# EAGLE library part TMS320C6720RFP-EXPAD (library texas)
Floating-Point Digital Signal Processors Source: http://focus.ti.com/lit/ds/symlink/tms320c6720.pdf
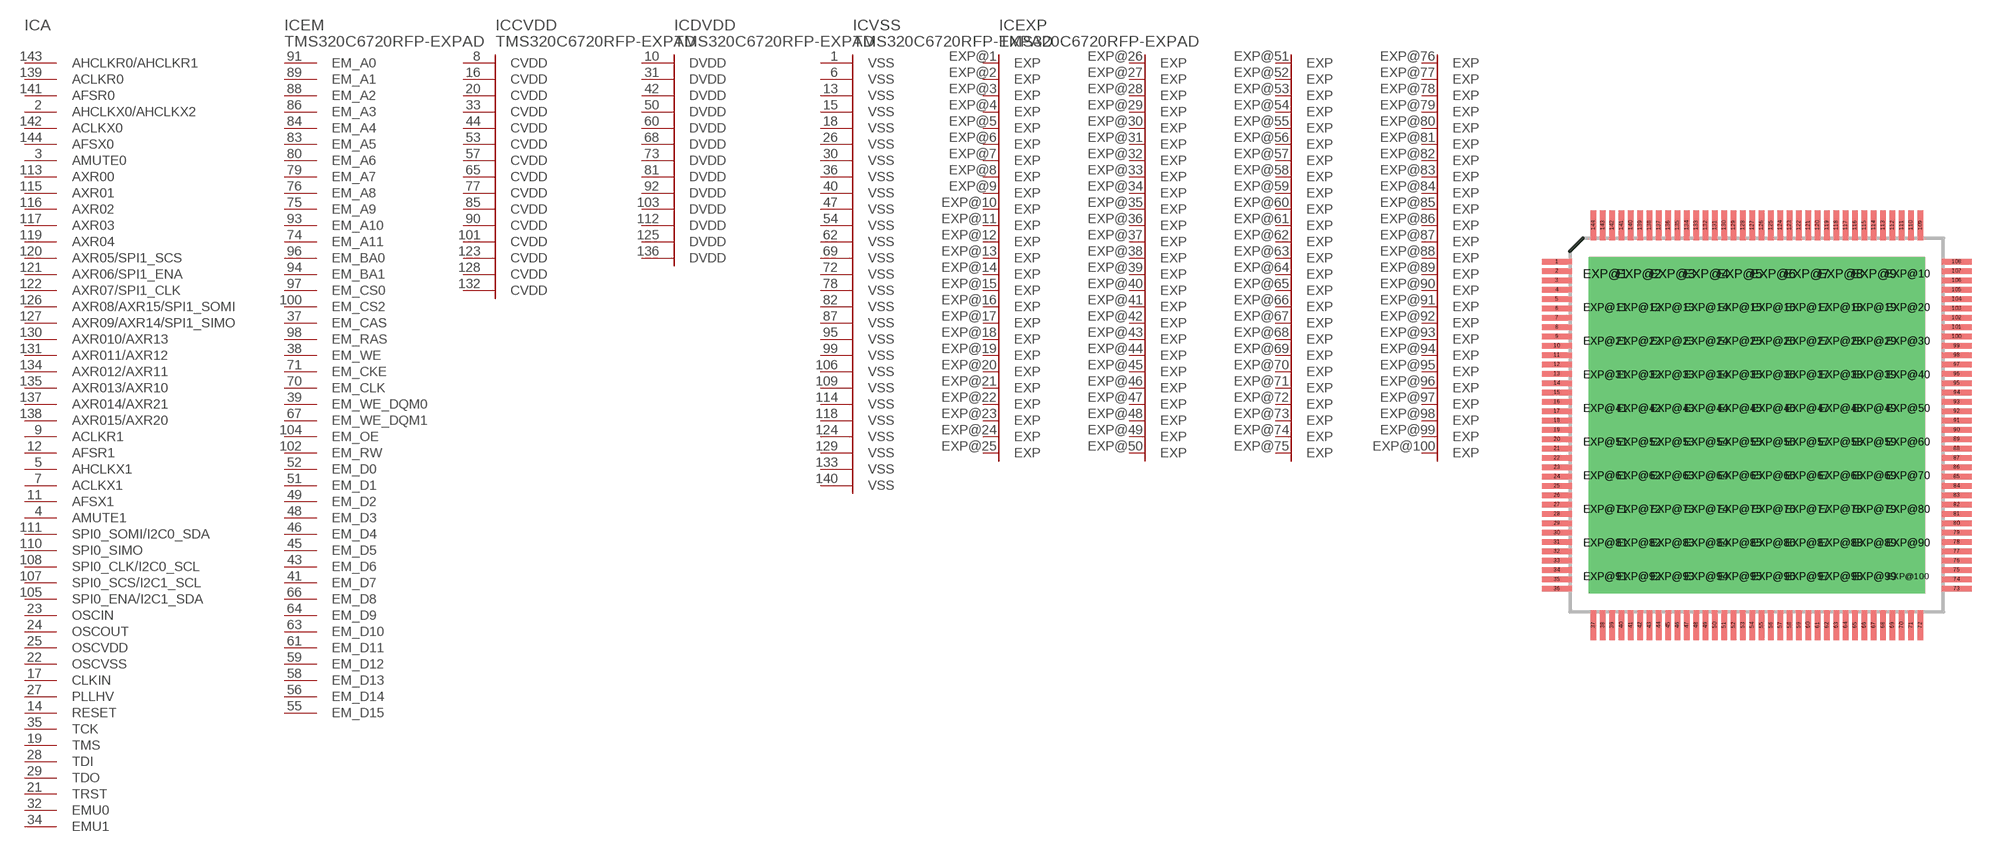
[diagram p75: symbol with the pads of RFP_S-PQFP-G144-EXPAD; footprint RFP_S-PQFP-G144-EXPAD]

Designator prefix IC; gates A=TMS320C6720-QFP-A EM=TMS320C6720-QFP-EM CVDD=TMS320C6720-QFP-CVDD DVDD=TMS320C6720-QFP-DVDD VSS=TMS320C6720-QFP-VSS EXP=EXP-100

## TMS320C6720RFP-EXPAD (OC_FARNELL: unknown; OC_NEWARK: unknown)  [RFP_S-PQFP-G144-EXPAD]
1  VSS:VSS  pwr
2  A:AHCLKX0/AHCLKX2
3  A:AMUTE0  out
4  A:AMUTE1  out
5  A:AHCLKX1
6  VSS:VSS  pwr
7  A:ACLKX1
8  CVDD:CVDD  pwr
9  A:ACLKR1
10  DVDD:DVDD  pwr
11  A:AFSX1
12  A:AFSR1
13  VSS:VSS  pwr
14  A:RESET  in
15  VSS:VSS  pwr
16  CVDD:CVDD  pwr
17  A:CLKIN  in
18  VSS:VSS  pwr
19  A:TMS  in
20  CVDD:CVDD  pwr
21  A:TRST  in
22  A:OSCVSS  pwr
23  A:OSCIN  in
24  A:OSCOUT  out
25  A:OSCVDD  pwr
26  VSS:VSS  pwr
27  A:PLLHV  pwr
28  A:TDI  in
29  A:TDO  hiz
30  VSS:VSS  pwr
31  DVDD:DVDD  pwr
32  A:EMU0
33  CVDD:CVDD  pwr
34  A:EMU1
35  A:TCK  in
36  VSS:VSS  pwr
37  EM:EM_CAS  out
38  EM:EM_WE  out
39  EM:EM_WE_DQM0  out
40  VSS:VSS  pwr
41  EM:EM_D7
42  DVDD:DVDD  pwr
43  EM:EM_D6
44  CVDD:CVDD  pwr
45  EM:EM_D5
46  EM:EM_D4
47  VSS:VSS  pwr
48  EM:EM_D3
49  EM:EM_D2
50  DVDD:DVDD  pwr
51  EM:EM_D1
52  EM:EM_D0
53  CVDD:CVDD  pwr
54  VSS:VSS  pwr
55  EM:EM_D15
56  EM:EM_D14
57  CVDD:CVDD  pwr
58  EM:EM_D13
59  EM:EM_D12
60  DVDD:DVDD  pwr
61  EM:EM_D11
62  VSS:VSS  pwr
63  EM:EM_D10
64  EM:EM_D9
65  CVDD:CVDD  pwr
66  EM:EM_D8
67  EM:EM_WE_DQM1  out
68  DVDD:DVDD  pwr
69  VSS:VSS  pwr
70  EM:EM_CLK  out
71  EM:EM_CKE  out
72  VSS:VSS  pwr
73  DVDD:DVDD  pwr
74  EM:EM_A11  out
75  EM:EM_A9  out
76  EM:EM_A8  out
77  CVDD:CVDD  pwr
78  VSS:VSS  pwr
79  EM:EM_A7  out
80  EM:EM_A6  out
81  DVDD:DVDD  pwr
82  VSS:VSS  pwr
83  EM:EM_A5  out
84  EM:EM_A4  out
85  CVDD:CVDD  pwr
86  EM:EM_A3  out
87  VSS:VSS  pwr
88  EM:EM_A2  out
89  EM:EM_A1  out
90  CVDD:CVDD  pwr
91  EM:EM_A0  out
92  DVDD:DVDD  pwr
93  EM:EM_A10  out
94  EM:EM_BA1  out
95  VSS:VSS  pwr
96  EM:EM_BA0  out
97  EM:EM_CS0  out
98  EM:EM_RAS  out
99  VSS:VSS  pwr
100  EM:EM_CS2  out
101  CVDD:CVDD  pwr
102  EM:EM_RW  out
103  DVDD:DVDD  pwr
104  EM:EM_OE  out
105  A:SPI0_ENA/I2C1_SDA
106  VSS:VSS  pwr
107  A:SPI0_SCS/I2C1_SCL
108  A:SPI0_CLK/I2C0_SCL
109  VSS:VSS  pwr
110  A:SPI0_SIMO
111  A:SPI0_SOMI/I2C0_SDA
112  DVDD:DVDD  pwr
113  A:AXR00
114  VSS:VSS  pwr
115  A:AXR01
116  A:AXR02
117  A:AXR03
118  VSS:VSS  pwr
119  A:AXR04
120  A:AXR05/SPI1_SCS
121  A:AXR06/SPI1_ENA
122  A:AXR07/SPI1_CLK
123  CVDD:CVDD  pwr
124  VSS:VSS  pwr
125  DVDD:DVDD  pwr
126  A:AXR08/AXR15/SPI1_SOMI
127  A:AXR09/AXR14/SPI1_SIMO
128  CVDD:CVDD  pwr
129  VSS:VSS  pwr
130  A:AXR010/AXR13
131  A:AXR011/AXR12
132  CVDD:CVDD  pwr
133  VSS:VSS  pwr
134  A:AXR012/AXR11
135  A:AXR013/AXR10
136  DVDD:DVDD  pwr
137  A:AXR014/AXR21
138  A:AXR015/AXR20
139  A:ACLKR0
140  VSS:VSS  pwr
141  A:AFSR0
142  A:ACLKX0
143  A:AHCLKR0/AHCLKR1
144  A:AFSX0
EXP@1  EXP:EXP  in
EXP@2  EXP:EXP  in
EXP@3  EXP:EXP  in
EXP@4  EXP:EXP  in
EXP@5  EXP:EXP  in
EXP@6  EXP:EXP  in
EXP@7  EXP:EXP  in
EXP@8  EXP:EXP  in
EXP@9  EXP:EXP  in
EXP@10  EXP:EXP  in
EXP@11  EXP:EXP  in
EXP@12  EXP:EXP  in
EXP@13  EXP:EXP  in
EXP@14  EXP:EXP  in
EXP@15  EXP:EXP  in
EXP@16  EXP:EXP  in
EXP@17  EXP:EXP  in
EXP@18  EXP:EXP  in
EXP@19  EXP:EXP  in
EXP@20  EXP:EXP  in
EXP@21  EXP:EXP  in
EXP@22  EXP:EXP  in
EXP@23  EXP:EXP  in
EXP@24  EXP:EXP  in
EXP@25  EXP:EXP  in
EXP@26  EXP:EXP  in
EXP@27  EXP:EXP  in
EXP@28  EXP:EXP  in
EXP@29  EXP:EXP  in
EXP@30  EXP:EXP  in
EXP@31  EXP:EXP  in
EXP@32  EXP:EXP  in
EXP@33  EXP:EXP  in
EXP@34  EXP:EXP  in
EXP@35  EXP:EXP  in
EXP@36  EXP:EXP  in
EXP@37  EXP:EXP  in
EXP@38  EXP:EXP  in
EXP@39  EXP:EXP  in
EXP@40  EXP:EXP  in
EXP@41  EXP:EXP  in
EXP@42  EXP:EXP  in
EXP@43  EXP:EXP  in
EXP@44  EXP:EXP  in
EXP@45  EXP:EXP  in
EXP@46  EXP:EXP  in
EXP@47  EXP:EXP  in
EXP@48  EXP:EXP  in
EXP@49  EXP:EXP  in
EXP@50  EXP:EXP  in
EXP@51  EXP:EXP  in
EXP@52  EXP:EXP  in
EXP@53  EXP:EXP  in
EXP@54  EXP:EXP  in
EXP@55  EXP:EXP  in
EXP@56  EXP:EXP  in
EXP@57  EXP:EXP  in
EXP@58  EXP:EXP  in
EXP@59  EXP:EXP  in
EXP@60  EXP:EXP  in
EXP@61  EXP:EXP  in
EXP@62  EXP:EXP  in
EXP@63  EXP:EXP  in
EXP@64  EXP:EXP  in
EXP@65  EXP:EXP  in
EXP@66  EXP:EXP  in
EXP@67  EXP:EXP  in
EXP@68  EXP:EXP  in
EXP@69  EXP:EXP  in
EXP@70  EXP:EXP  in
EXP@71  EXP:EXP  in
EXP@72  EXP:EXP  in
EXP@73  EXP:EXP  in
EXP@74  EXP:EXP  in
EXP@75  EXP:EXP  in
EXP@76  EXP:EXP  in
EXP@77  EXP:EXP  in
EXP@78  EXP:EXP  in
EXP@79  EXP:EXP  in
EXP@80  EXP:EXP  in
EXP@81  EXP:EXP  in
EXP@82  EXP:EXP  in
EXP@83  EXP:EXP  in
EXP@84  EXP:EXP  in
EXP@85  EXP:EXP  in
EXP@86  EXP:EXP  in
EXP@87  EXP:EXP  in
EXP@88  EXP:EXP  in
EXP@89  EXP:EXP  in
EXP@90  EXP:EXP  in
EXP@91  EXP:EXP  in
EXP@92  EXP:EXP  in
EXP@93  EXP:EXP  in
EXP@94  EXP:EXP  in
EXP@95  EXP:EXP  in
EXP@96  EXP:EXP  in
EXP@97  EXP:EXP  in
EXP@98  EXP:EXP  in
EXP@99  EXP:EXP  in
EXP@100  EXP:EXP  in

## Footprint RFP_S-PQFP-G144-EXPAD (pad centres in mm)
RFP_S-PQFP-G144 PowerPAD PLASTIC QUAD FLATPACK Source: http://focus.ti.com/lit/ds/symlink/tms320c6720.pdf Auto generated by make-symbol-device-package-bsdl.ulp Rev. 29
smd 1.6 x 0.3: 1 -10.7,8.75; 2 -10.7,8.25; 3 -10.7,7.75; 4 -10.7,7.25; 5 -10.7,6.75; 6 -10.7,6.25; 7 -10.7,5.75; 8 -10.7,5.25; 9 -10.7,4.75; 10 -10.7,4.25; 11 -10.7,3.75; 12 -10.7,3.25; 13 -10.7,2.75; 14 -10.7,2.25; 15 -10.7,1.75; 16 -10.7,1.25; 17 -10.7,0.75; 18 -10.7,0.25; 19 -10.7,-0.25; 20 -10.7,-0.75; 21 -10.7,-1.25; 22 -10.7,-1.75; 23 -10.7,-2.25; 24 -10.7,-2.75; 25 -10.7,-3.25; 26 -10.7,-3.75; 27 -10.7,-4.25; 28 -10.7,-4.75; 29 -10.7,-5.25; 30 -10.7,-5.75; 31 -10.7,-6.25; 32 -10.7,-6.75; 33 -10.7,-7.25; 34 -10.7,-7.75; 35 -10.7,-8.25; 36 -10.7,-8.75; 73 10.7,-8.75; 74 10.7,-8.25; 75 10.7,-7.75; 76 10.7,-7.25; 77 10.7,-6.75; 78 10.7,-6.25; 79 10.7,-5.75; 80 10.7,-5.25; 81 10.7,-4.75; 82 10.7,-4.25; 83 10.7,-3.75; 84 10.7,-3.25; 85 10.7,-2.75; 86 10.7,-2.25; 87 10.7,-1.75; 88 10.7,-1.25; 89 10.7,-0.75; 90 10.7,-0.25; 91 10.7,0.25; 92 10.7,0.75; 93 10.7,1.25; 94 10.7,1.75; 95 10.7,2.25; 96 10.7,2.75; 97 10.7,3.25; 98 10.7,3.75; 99 10.7,4.25; 100 10.7,4.75; 101 10.7,5.25; 102 10.7,5.75; 103 10.7,6.25; 104 10.7,6.75; 105 10.7,7.25; 106 10.7,7.75; 107 10.7,8.25; 108 10.7,8.75
smd 0.3 x 1.6: 37 -8.75,-10.7; 38 -8.25,-10.7; 39 -7.75,-10.7; 40 -7.25,-10.7; 41 -6.75,-10.7; 42 -6.25,-10.7; 43 -5.75,-10.7; 44 -5.25,-10.7; 45 -4.75,-10.7; 46 -4.25,-10.7; 47 -3.75,-10.7; 48 -3.25,-10.7; 49 -2.75,-10.7; 50 -2.25,-10.7; 51 -1.75,-10.7; 52 -1.25,-10.7; 53 -0.75,-10.7; 54 -0.25,-10.7; 55 0.25,-10.7; 56 0.75,-10.7; 57 1.25,-10.7; 58 1.75,-10.7; 59 2.25,-10.7; 60 2.75,-10.7; 61 3.25,-10.7; 62 3.75,-10.7; 63 4.25,-10.7; 64 4.75,-10.7; 65 5.25,-10.7; 66 5.75,-10.7; 67 6.25,-10.7; 68 6.75,-10.7; 69 7.25,-10.7; 70 7.75,-10.7; 71 8.25,-10.7; 72 8.75,-10.7; 109 8.75,10.7; 110 8.25,10.7; 111 7.75,10.7; 112 7.25,10.7; 113 6.75,10.7; 114 6.25,10.7; 115 5.75,10.7; 116 5.25,10.7; 117 4.75,10.7; 118 4.25,10.7; 119 3.75,10.7; 120 3.25,10.7; 121 2.75,10.7; 122 2.25,10.7; 123 1.75,10.7; 124 1.25,10.7; 125 0.75,10.7; 126 0.25,10.7; 127 -0.25,10.7; 128 -0.75,10.7; 129 -1.25,10.7; 130 -1.75,10.7; 131 -2.25,10.7; 132 -2.75,10.7; 133 -3.25,10.7; 134 -3.75,10.7; 135 -4.25,10.7; 136 -4.75,10.7; 137 -5.25,10.7; 138 -5.75,10.7; 139 -6.25,10.7; 140 -6.75,10.7; 141 -7.25,10.7; 142 -7.75,10.7; 143 -8.25,10.7; 144 -8.75,10.7
drill 0.3 pad 1.8 square: EXP@1 -8.1,8.1; EXP@2 -6.3,8.1; EXP@3 -4.5,8.1; EXP@4 -2.7,8.1; EXP@5 -0.9,8.1; EXP@6 0.9,8.1; EXP@7 2.7,8.1; EXP@8 4.5,8.1; EXP@9 6.3,8.1; EXP@10 8.1,8.1; EXP@11 -8.1,6.3; EXP@12 -6.3,6.3; EXP@13 -4.5,6.3; EXP@14 -2.7,6.3; EXP@15 -0.9,6.3; EXP@16 0.9,6.3; EXP@17 2.7,6.3; EXP@18 4.5,6.3; EXP@19 6.3,6.3; EXP@20 8.1,6.3; EXP@21 -8.1,4.5; EXP@22 -6.3,4.5; EXP@23 -4.5,4.5; EXP@24 -2.7,4.5; EXP@25 -0.9,4.5; EXP@26 0.9,4.5; EXP@27 2.7,4.5; EXP@28 4.5,4.5; EXP@29 6.3,4.5; EXP@30 8.1,4.5; EXP@31 -8.1,2.7; EXP@32 -6.3,2.7; EXP@33 -4.5,2.7; EXP@34 -2.7,2.7; EXP@35 -0.9,2.7; EXP@36 0.9,2.7; EXP@37 2.7,2.7; EXP@38 4.5,2.7; EXP@39 6.3,2.7; EXP@40 8.1,2.7; EXP@41 -8.1,0.9; EXP@42 -6.3,0.9; EXP@43 -4.5,0.9; EXP@44 -2.7,0.9; EXP@45 -0.9,0.9; EXP@46 0.9,0.9; EXP@47 2.7,0.9; EXP@48 4.5,0.9; EXP@49 6.3,0.9; EXP@50 8.1,0.9; EXP@51 -8.1,-0.9; EXP@52 -6.3,-0.9; EXP@53 -4.5,-0.9; EXP@54 -2.7,-0.9; EXP@55 -0.9,-0.9; EXP@56 0.9,-0.9; EXP@57 2.7,-0.9; EXP@58 4.5,-0.9; EXP@59 6.3,-0.9; EXP@60 8.1,-0.9; EXP@61 -8.1,-2.7; EXP@62 -6.3,-2.7; EXP@63 -4.5,-2.7; EXP@64 -2.7,-2.7; EXP@65 -0.9,-2.7; EXP@66 0.9,-2.7; EXP@67 2.7,-2.7; EXP@68 4.5,-2.7; EXP@69 6.3,-2.7; EXP@70 8.1,-2.7; EXP@71 -8.1,-4.5; EXP@72 -6.3,-4.5; EXP@73 -4.5,-4.5; EXP@74 -2.7,-4.5; EXP@75 -0.9,-4.5; EXP@76 0.9,-4.5; EXP@77 2.7,-4.5; EXP@78 4.5,-4.5; EXP@79 6.3,-4.5; EXP@80 8.1,-4.5; EXP@81 -8.1,-6.3; EXP@82 -6.3,-6.3; EXP@83 -4.5,-6.3; EXP@84 -2.7,-6.3; EXP@85 -0.9,-6.3; EXP@86 0.9,-6.3; EXP@87 2.7,-6.3; EXP@88 4.5,-6.3; EXP@89 6.3,-6.3; EXP@90 8.1,-6.3; EXP@91 -8.1,-8.1; EXP@92 -6.3,-8.1; EXP@93 -4.5,-8.1; EXP@94 -2.7,-8.1; EXP@95 -0.9,-8.1; EXP@96 0.9,-8.1; EXP@97 2.7,-8.1; EXP@98 4.5,-8.1; EXP@99 6.3,-8.1; EXP@100 8.1,-8.1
